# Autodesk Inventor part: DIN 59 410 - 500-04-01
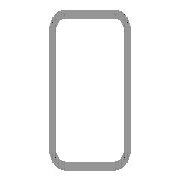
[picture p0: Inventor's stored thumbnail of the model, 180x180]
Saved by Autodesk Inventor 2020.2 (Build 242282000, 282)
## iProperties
Manager: www.cadconsulting.pl
Company: Fabian Stasiak CAD Consulting
Created: 2015-02
Part Number: DIN 59 410 - 500-04-01
Material: Stal
Description: Rurki stalowe o przekroju prostokątnym formowane na gorąco
Document SubType Name: Modellieren
Standard: DIN 59 410
Designer: F.Stasiak
Standards Organization: DIN
Language: pl-PL
Size Designation: 100x50x4.5-1680
Categories: <MemberInstance><Categories><Category DisplayName="Kształtowniki konstrukcyjne" InternalName="089c4875-fa83-4c05-b084-43b9cc11f5ed" Mnemonic="GRDR"><CategoryPar
Stock Number: 100x50x4.5
Density: 7.85 g/cm^3
Appearance: Płyta
IsCustomPart: 1
G_L: 1800,000 mm
Author: F.Stasiak
Subject: Zbiór ćwiczeń. Autodesk Inventor 2020. Kurs podstawowy
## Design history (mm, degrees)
node "Płaszczyzna początkowa"
node "Płaszczyzna końcowa"
sketch "Szkic1"
  geometry: L1 (-20, 60)-(20, 60); L2 (30, 50)-(30, -50); L3 (20, -60)-(-20, -60); L4 (-30, -50)-(-30, 50); L5 (-44.61, 0)-(44.61, 0) reference; L6 (0, -86.61)-(0, 86.61) reference; L7 (-20, 55)-(20, 55); L8 (25, 50)-(25, -50); L9 (20, -55)-(-20, -55); L10 (-25, -50)-(-25, 50); A1 r 10 centre (-20, 50) between (-20, 60) and (-30, 50); A2 r 10 centre (20, 50) between (30, 50) and (20, 60); A3 r 10 centre (20, -50) between (20, -60) and (30, -50); A4 r 10 centre (-20, -50) between (-30, -50) and (-20, -60); A5 r 5 centre (-20, 50) between (-20, 55) and (-25, 50); A6 r 5 centre (20, 50) between (25, 50) and (20, 55); A7 r 5 centre (20, -50) between (20, -55) and (25, -50); A8 r 5 centre (-20, -50) between (-25, -50) and (-20, -55); 3 further points
  constraints: 16 end point, 16 point on circle, 8 centre point, 8 tangent, 6 point on line, 4 parallel, 3 equal radius, 2 perpendicular, 1 horizontal, 7 other
  dimensions: "b" = 60 distance of point (-30, 60) point (30, 60); "ParH" = 120 distance of point (30, 60) point (30, -60); "msp_r" = 10 radius of A1 (= 2 x ParT); "d8" = 30 distance between parallel lines of L4 L6 (= 0.5 x b); "d9" = 60 distance between parallel lines of L5 L1 (= 0.5 x ParH); "d10" = 5 distance between parallel lines of L4 L10 (= ParT)
extrude "Bryła" new body sketch "Szkic1" taper "d4" = 0 deg; stored distance "NLG" = 10
node "Driven Length"
  sketch "Sketch2"
    geometry: L1 (0, 0)-(10, 0) reference
    constraints: 2 end point, 1 horizontal
  workplane "Work Plane3"
  sketch "Sketch3"
    geometry: L1 (-2, 0)-(12, 0) reference; L2 (-2, 1800)-(12, 1800) reference
    dimensions: "d14" = 1800 distance between parallel lines of L1 L2 (derived)
sketch "Szkic4"
  geometry: L1 (0, 100)-(0, 0) reference; L2 (1800, 100)-(1800, 0) reference; L3 (0, 50)-(1800, 50); 3 further points
  constraints: 2 end point, 2 midpoint, 2 point on line, 1 horizontal
  dimensions: "d15" = 60 distance from line of L1 point (60, 50); "d16" = 60 distance from line of L2 point (1740, 50)
hole "Otwór1" sketch "Szkic4" at (900, 50), (1740, 50), (60, 50) diameter "d17" = 50; stored, may be unused: countersink angle "d21" = 90 deg, drill point angle "d23" = 118 deg; dims "d18" = 6, "d19" = 4, "d20" = 2, "d22" = 8
sketch "Szkic5"
  geometry: L1 (0, 10)-(1800, 10) reference; L2 (0, -110)-(1800, -110) reference; L3 (63.629, 10)-(10, -35); L4 (10, -35)-(10, -65); L5 (10, -65)-(63.629, -110); L6 (0, 10)-(0, -110); C1 r 25 at (60, -50) reference; 1 further point
  constraints: 8 end point, 2 point on line, 1 equal length, 1 perpendicular, 1 vertical, 1 vertical alignment
  dimensions: "d24" = 50 distance from line of C1.centre L4; "d25" = 130 deg angle of L3 L4; "d26" = 30 distance of L3.end L4.end
extrude "Wyciągnięcie proste2" cut sketch "Szkic5" extent not by distance; stored distance "d27" = 10; taper "d28" = 0 deg
node "Płaszczyzna konstrukcyjna5"
  node "Oś konstrukcyjna1"
mirror "Odbicie lustrzane1"
body "Solid1"
other parameters: "ParT" = 5, "G_OFFSET_START" = 0 [user parameter; used in 1 equation term], "G_OFFSET_END" = 0 [user parameter; used in 1 equation term], "d11" = 0 (computed from G_OFFSET_START), "G_L" = 1800 (= d14) [user parameter], "d13" = 90 deg, "d29" = 0
